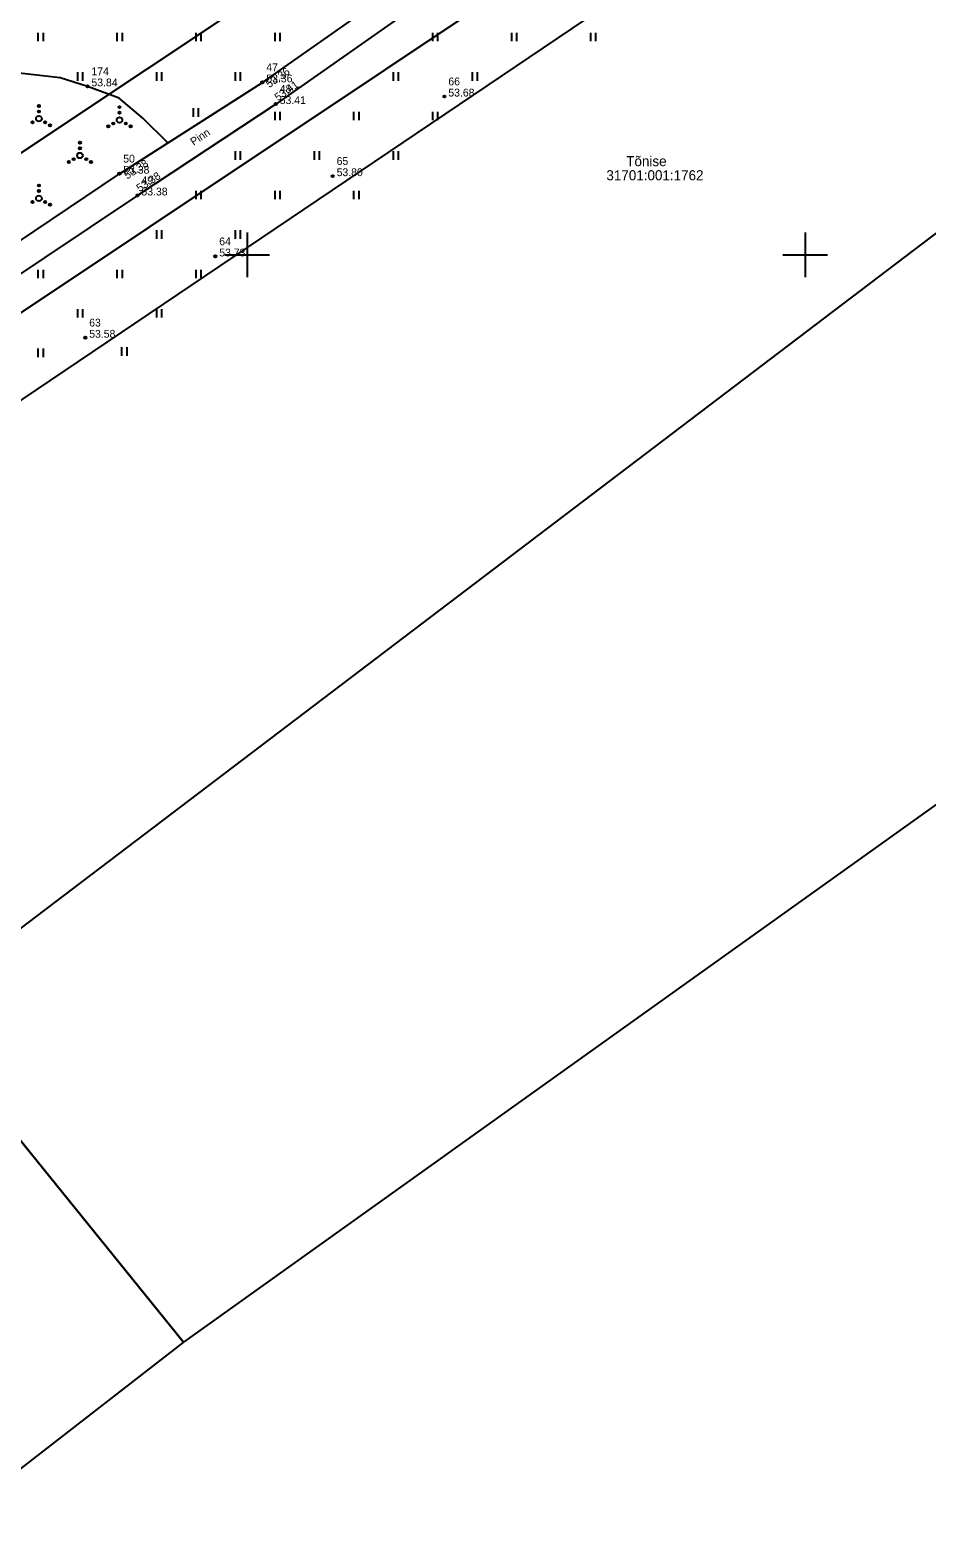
# Model space of a CAD drawing. Extents: x 538599 to 541973, y 6559689 to 6564516.
# Drawn here: x 540530.5 to 540610.9, y 6561085.1 to 6561220.1 of the extents above; entities that cross this region are included whole.
import ezdxf

# ---------------------------------------------------------------- set-up
doc = ezdxf.new("R2010")
doc.units = 0
for name, color, linetype in [('HALJASTUS', 7, 'Continuous'), ('KORGUS-EH2000', 7, 'Continuous'), ('MOOTKORG-EH2000', 7, 'Continuous'), ('MOOTMPUNKT', 7, 'Continuous'), ('MOOTNR', 7, 'Continuous'), ('MOOTPIIR', 7, 'Continuous'), ('PIIR', 7, 'Continuous'), ('TEE', 7, 'Continuous'), ('VORK', 7, 'Continuous'), ('VORMISTUS', 7, 'Continuous')]:
    doc.layers.add(name, color=color, linetype=linetype)

msp = doc.modelspace()

# ---------------------------------------------------------------- linework, layer by layer
at = {"layer": 'HALJASTUS'}
for p, q in [((540531.25, 6561219.9), (540531.25, 6561219.14)), ((540531.7, 6561219.9), (540531.7, 6561219.14)), ((540538.32, 6561219.9), (540538.32, 6561219.14)), ((540538.78, 6561219.9), (540538.78, 6561219.14)), ((540545.39, 6561219.9), (540545.39, 6561219.14)), ((540545.85, 6561219.9), (540545.85, 6561219.14)), ((540552.46, 6561219.9), (540552.46, 6561219.14)), ((540552.92, 6561219.9), (540552.92, 6561219.14)), ((540566.61, 6561219.9), (540566.61, 6561219.14)), ((540567.06, 6561219.9), (540567.06, 6561219.14)), ((540573.68, 6561219.9), (540573.68, 6561219.14)), ((540574.13, 6561219.9), (540574.13, 6561219.14)), ((540580.75, 6561219.9), (540580.75, 6561219.14)), ((540581.2, 6561219.9), (540581.2, 6561219.14)), ((540534.79, 6561216.36), (540534.79, 6561215.6)), ((540535.24, 6561216.36), (540535.24, 6561215.6)), ((540541.86, 6561216.36), (540541.86, 6561215.6)), ((540542.31, 6561216.36), (540542.31, 6561215.6)), ((540548.93, 6561216.36), (540548.93, 6561215.6)), ((540549.38, 6561216.36), (540549.38, 6561215.6)), ((540563.07, 6561216.36), (540563.07, 6561215.6)), ((540563.52, 6561216.36), (540563.52, 6561215.6)), ((540570.14, 6561216.36), (540570.14, 6561215.6)), ((540570.6, 6561216.36), (540570.6, 6561215.6)), ((540545.14, 6561213.14), (540545.14, 6561212.38)), ((540545.59, 6561213.14), (540545.59, 6561212.38)), ((540552.46, 6561212.83), (540552.46, 6561212.06)), ((540552.92, 6561212.83), (540552.92, 6561212.06)), ((540559.53, 6561212.83), (540559.53, 6561212.06)), ((540559.99, 6561212.83), (540559.99, 6561212.06)), ((540566.61, 6561212.83), (540566.61, 6561212.06)), ((540567.06, 6561212.83), (540567.06, 6561212.06)), ((540548.93, 6561209.29), (540548.93, 6561208.53)), ((540549.38, 6561209.29), (540549.38, 6561208.53)), ((540556, 6561209.29), (540556, 6561208.53)), ((540556.45, 6561209.29), (540556.45, 6561208.53)), ((540563.07, 6561209.29), (540563.07, 6561208.53)), ((540563.52, 6561209.29), (540563.52, 6561208.53)), ((540545.39, 6561205.75), (540545.39, 6561204.99)), ((540545.85, 6561205.75), (540545.85, 6561204.99)), ((540552.46, 6561205.75), (540552.46, 6561204.99)), ((540552.92, 6561205.75), (540552.92, 6561204.99)), ((540559.53, 6561205.75), (540559.53, 6561204.99)), ((540559.99, 6561205.75), (540559.99, 6561204.99)), ((540541.86, 6561202.22), (540541.86, 6561201.46)), ((540542.31, 6561202.22), (540542.31, 6561201.46)), ((540548.93, 6561202.22), (540548.93, 6561201.46)), ((540549.38, 6561202.22), (540549.38, 6561201.46)), ((540531.25, 6561198.68), (540531.25, 6561197.92)), ((540531.7, 6561198.68), (540531.7, 6561197.92)), ((540538.32, 6561198.68), (540538.32, 6561197.92)), ((540538.78, 6561198.68), (540538.78, 6561197.92)), ((540545.39, 6561198.68), (540545.39, 6561197.92)), ((540545.85, 6561198.68), (540545.85, 6561197.92)), ((540534.79, 6561195.15), (540534.79, 6561194.39)), ((540535.24, 6561195.15), (540535.24, 6561194.39)), ((540541.86, 6561195.15), (540541.86, 6561194.39)), ((540542.31, 6561195.15), (540542.31, 6561194.39)), ((540531.25, 6561191.61), (540531.25, 6561190.85)), ((540531.7, 6561191.61), (540531.7, 6561190.85)), ((540538.74, 6561191.73), (540538.74, 6561190.97)), ((540539.2, 6561191.73), (540539.2, 6561190.97))]:
    msp.add_line(p, q, dxfattribs=at)
msp.add_lwpolyline([(540542.89, 6561210.05), (540540.64, 6561212.24), (540538.53, 6561214.05), (540535.69, 6561215.1), (540533.25, 6561215.86), (540528.8, 6561216.38), (540524.71, 6561215.83), (540520.83, 6561215.24), (540514.94, 6561213.71), (540511.97, 6561212.61), (540509.89, 6561210.71), (540504.95, 6561204.96), (540500.47, 6561200.78), (540499.56, 6561198.86), (540499.42, 6561196.98), (540500.37, 6561193.42), (540499.93, 6561192.09), (540496.98, 6561189.65), (540491.24, 6561186.18)], dxfattribs=at)
for centre, radius in [((540531.33, 6561213.35), 0.1), ((540531.33, 6561212.85), 0.1), ((540538.55, 6561213.24), 0.1), ((540538.55, 6561212.74), 0.1), ((540530.76, 6561211.87), 0.1), ((540531.33, 6561212.2), 0.25), ((540531.89, 6561211.87), 0.1), ((540532.33, 6561211.62), 0.1), ((540537.55, 6561211.52), 0.1), ((540537.99, 6561211.77), 0.1), ((540538.55, 6561212.09), 0.25), ((540539.12, 6561211.77), 0.1), ((540539.55, 6561211.52), 0.1), ((540535.01, 6561210.06), 0.1), ((540534.45, 6561208.58), 0.1), ((540535.01, 6561208.91), 0.25), ((540535.01, 6561209.56), 0.1), ((540535.58, 6561208.58), 0.1), ((540534.01, 6561208.33), 0.1), ((540536.01, 6561208.33), 0.1), ((540531.33, 6561206.22), 0.1), ((540530.76, 6561204.75), 0.1), ((540531.33, 6561205.07), 0.25), ((540531.33, 6561205.72), 0.1), ((540531.89, 6561204.75), 0.1), ((540532.33, 6561204.5), 0.1)]:
    msp.add_circle(centre, radius, dxfattribs=at)
at = {"layer": 'KORGUS-EH2000'}
for centre in [(540551.36, 6561215.46), (540535.69, 6561215.1), (540567.67, 6561214.19), (540552.56, 6561213.52), (540538.54, 6561207.28), (540557.66, 6561207.06), (540540.17, 6561205.33), (540547.14, 6561199.87), (540535.49, 6561192.59)]:
    msp.add_circle(centre, 0.1, dxfattribs=at)
at = {"layer": 'MOOTMPUNKT'}
for centre in [(540551.36, 6561215.46), (540535.69, 6561215.1), (540567.67, 6561214.19), (540552.56, 6561213.52), (540538.54, 6561207.28), (540557.66, 6561207.06), (540540.17, 6561205.33), (540547.14, 6561199.87), (540535.49, 6561192.59)]:
    msp.add_circle(centre, 0.1, dxfattribs=at)
at = {"layer": 'MOOTPIIR'}
msp.add_lwpolyline([(540384.89, 6561443.84), (540403.97, 6561422.47), (540424.3, 6561399.7), (540444.64, 6561376.93), (540453.18, 6561363.99), (540470.99, 6561343.69), (540492.69, 6561318.98), (540511.77, 6561294.34), (540521.97, 6561279.18), (540525.59, 6561267.95), (540536.49, 6561252.79), (540542.77, 6561231.93), (540526.6, 6561219.05), (540510.62, 6561213.47), (540498.26, 6561199.2), (540484.56, 6561192.98), (540479.62, 6561185.62), (540478.41, 6561178.33), (540490.46, 6561165.83), (540493.58, 6561162.6), (540531.11, 6561187.91), (540582.87, 6561222.82), (540621.74, 6561247.75)], dxfattribs=at)
at = {"layer": 'PIIR'}
for points in [[(540491.21, 6561183.5), (540566.07, 6561233.36), (540528.84, 6561281.85), (540494.34, 6561324.62), (540458.27, 6561368.69), (540424.68, 6561408.57), (540384.55, 6561455.73), (540346.17, 6561499.11), (540330.12, 6561517.14), (540337.36, 6561523.32), (540348.28, 6561532.96), (540364.11, 6561514.94), (540353.14, 6561505.27), (540391.51, 6561461.86), (540431.74, 6561414.74), (540465.17, 6561374.89), (540501.31, 6561330.86), (540535.92, 6561287.97), (540573.77, 6561238.75), (540640.63, 6561283.66), (540646.74, 6561272.89), (540499, 6561174.36)], [(540458.8, 6561220.37), (540528.84, 6561281.85), (540566.07, 6561233.36), (540491.21, 6561183.5)], [(540490.55, 6561169.03), (540499, 6561174.36), (540646.74, 6561272.89), (540687.02, 6561204.55), (540544.29, 6561102.63)], [(539697.33, 6560658.69), (539847.51, 6560731.53), (540490.55, 6561169.03), (540544.29, 6561102.63), (540118.77, 6560772.59), (539949.96, 6560644.18), (539786.62, 6560520.8), (539742.09, 6560589.51)]]:
    msp.add_lwpolyline(points, close=True, dxfattribs=at)
at = {"layer": 'TEE'}
for points in [[(540651.02, 6561277.76), (540649.3, 6561277.32), (540647.95, 6561276.71), (540637.2, 6561268.88), (540625.63, 6561261.53), (540617.28, 6561256.23), (540613.09, 6561253.42), (540601, 6561245.41), (540588.33, 6561236.98), (540576.97, 6561229.56), (540565.17, 6561222.34), (540552.56, 6561213.52), (540540.17, 6561205.33), (540527.67, 6561197), (540515.61, 6561188.75), (540503.25, 6561180.45), (540486.57, 6561169.87)], [(540484.99, 6561171.5), (540501.86, 6561182.66), (540513.62, 6561190.83), (540526.37, 6561199.09), (540538.54, 6561207.28), (540551.36, 6561215.46), (540563.47, 6561223.95)]]:
    msp.add_lwpolyline(points, dxfattribs=at)
at = {"layer": 'VORK'}
for p, q in [((540550, 6561202), (540550, 6561198)), ((540600, 6561202), (540600, 6561198)), ((540548, 6561200), (540552, 6561200)), ((540598, 6561200), (540602, 6561200))]:
    msp.add_line(p, q, dxfattribs=at)
at = {"layer": 'VORMISTUS'}
msp.add_lwpolyline([(540437.61, 6561637.11), (540710.79, 6561277.18), (540482.18, 6561103.67), (540209, 6561463.6)], close=True, dxfattribs=at)

# ---------------------------------------------------------------- texts
at = {"layer": 'KORGUS-EH2000'}
for s, rotation, p in [('53.36', 35.0456, (540551.97, 6561214.93)), ('53.41', 34.9871, (540552.75, 6561213.75)), ('53.38', 32.5547, (540539.24, 6561206.75)), ('53.38', 33.4645, (540540.36, 6561205.62))]:
    msp.add_text(s, height=0.7, rotation=rotation, dxfattribs=at).set_placement(p)
for s, p in [('53.84', (540536.04, 6561215.1)), ('53.68', (540568.02, 6561214.19)), ('53.80', (540558.01, 6561207.06)), ('53.73', (540547.49, 6561199.87)), ('53.58', (540535.84, 6561192.59))]:
    msp.add_text(s, height=0.7, dxfattribs=at).set_placement(p)
at = {"layer": 'MOOTKORG-EH2000'}
for s, p in [('53.84', (540536.04, 6561215.1)), ('53.36', (540551.71, 6561215.46)), ('53.41', (540552.91, 6561213.52)), ('53.68', (540568.02, 6561214.19)), ('53.38', (540538.89, 6561207.28)), ('53.80', (540558.01, 6561207.06)), ('53.38', (540540.52, 6561205.33)), ('53.73', (540547.49, 6561199.87)), ('53.58', (540535.84, 6561192.59))]:
    msp.add_text(s, height=0.7, dxfattribs=at).set_placement(p)
at = {"layer": 'MOOTNR'}
for s, p in [('174', (540536.04, 6561216.1)), ('47', (540551.71, 6561216.46)), ('66', (540568.02, 6561215.19)), ('48', (540552.91, 6561214.52)), ('50', (540538.89, 6561208.28)), ('65', (540558.01, 6561208.06)), ('49', (540540.52, 6561206.33)), ('64', (540547.49, 6561200.87)), ('63', (540535.84, 6561193.59))]:
    msp.add_text(s, height=0.7, dxfattribs=at).set_placement(p)
at = {"layer": 'PIIR'}
for s, p in [('Tõnise', (540583.96, 6561207.95)), ('31701:001:1762', (540582.18, 6561206.69))]:
    msp.add_text(s, height=0.9, rotation=360, dxfattribs=at).set_placement(p)
at = {"layer": 'TEE'}
msp.add_text('Pinn', height=0.7, rotation=33.4645, dxfattribs=at).set_placement((540545.19, 6561209.77))

doc.saveas('drawing.dxf')
